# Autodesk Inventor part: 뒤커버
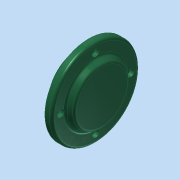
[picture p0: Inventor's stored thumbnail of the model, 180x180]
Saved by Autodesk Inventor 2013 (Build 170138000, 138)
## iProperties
Created: 2015-11
Part Number: 뒤커버
Material: 알루미늄 6061
Document SubType Name: Modeling
Designer: mduedu
Density: 2.71 g/cm^3
Mass: 309.118 g
Surface Area: 231.216 cm^2
Volume: 114.066 cm^3
Author: mduedu
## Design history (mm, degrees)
sketch "스케치1"
  geometry: C1 r 50 at (0, 0); 1 further point
  constraints: 1 centre point, 1 coincident
  dimensions: "d42" = 100 diameter of C1
extrude "돌출1" new body sketch "스케치1" distance "d3" = 8; taper "d4" = 0 deg
sketch "스케치2"
  geometry: C1 r 35 at (0, 0); 1 further point
  constraints: 1 centre point, 1 coincident
  dimensions: "d5" = 70 diameter of C1
extrude "돌출2" join sketch "스케치2" distance "d6" = 7; taper "d7" = -30 deg
sketch "스케치5" dims "d44" = 80
  geometry: 3 further points
  constraints: 2 vertical alignment, 1 coincident, 2 other
hole "구멍3" sketch "스케치5" at (0, 40) diameter "d45" = 4.5; stored, may be unused: countersink angle "d49" = 90 deg, drill point angle "d51" = 118 deg; dims "d46" = 6, "d47" = 8, "d48" = 4.4, "d50" = 8
sketch "스케치4"
  geometry: C1 r 35 at (0, 0); 1 further point
  constraints: 1 centre point, 1 coincident
  dimensions: "d21" = 70 diameter of C1
extrude "돌출3" join sketch "스케치4" distance "d23" = 12; taper "d24" = 0 deg
hole "구멍2" diameter "d27" = 30; stored, may be unused: countersink angle "d31" = 90 deg, drill point angle "d33" = 0 deg; dims "d25" = 10, "d26" = 10, "d28" = 6, "d29" = 40, "d30" = 12, "d32" = 15
fillet "모깎기3" dims "d36" = 3
fillet "모깎기4" dims "d37" = 3
fillet "모깎기5" dims "d38" = 0.3
chamfer "모따기1" distance "d39" = 1; stored, may be unused: second distance "d40" = 2, angle "d41" = 45 deg
node "솔리드1"
pattern_circular "원형 패턴2" dims angle "d53" = 360 deg
